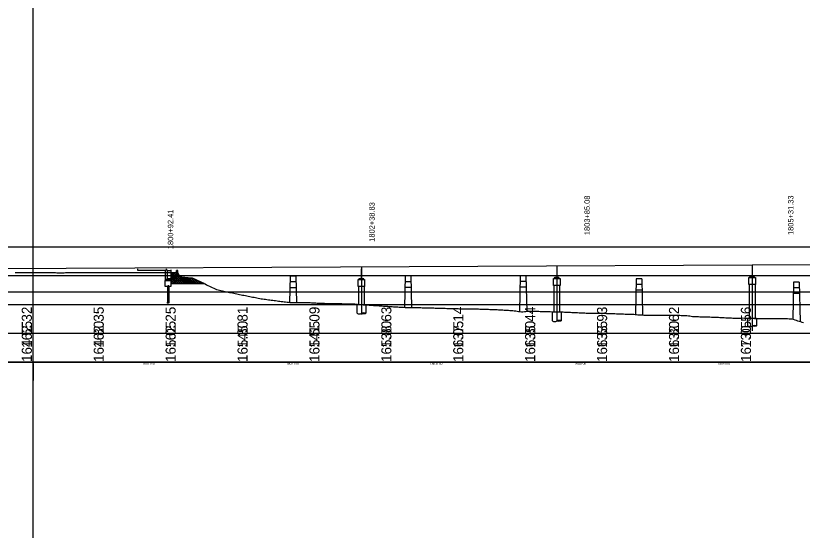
# Model space of a CAD drawing. Extents: x 2126510 to 2136144, y 865066 to 868066.
# Drawn here: x 2128457 to 2129003, y 866497 to 866855 of the extents above; entities that cross this region are included whole.
import ezdxf

# ---------------------------------------------------------------- set-up
doc = ezdxf.new("R2010")
doc.units = 0
for name, color, linetype in [('RD_DTM_BkLn1', 7, 'Continuous'), ('RD_EX_Bldg', 7, 'Continuous'), ('RD_EX_Bridge', 7, 'Continuous'), ('RD_EX_DR_Pipe', 7, 'Continuous'), ('RD_EX_GuardRail', 7, 'Continuous'), ('RD_EX_H2O', 7, 'Continuous'), ('RD_EX_Misc', 7, 'Continuous'), ('RD_EX_Misc_Golf_Fairway', 7, 'Continuous'), ('RD_EX_VEG', 7, 'Continuous'), ('RD_HC_Data', 7, 'Continuous'), ('RD_HC_txCode', 7, 'Continuous')]:
    doc.layers.add(name, color=color, linetype=linetype)

msp = doc.modelspace()

# ---------------------------------------------------------------- linework, layer by layer
at = {"layer": 'RD_DTM_BkLn1'}
for p, q in [((2128541.13, 866678.82), (2128541.13, 866677.82)), ((2128541.13, 866677.82), (2128561.13, 866677.92)), ((2128560.46, 866677.92), (2128560.46, 866670.48)), ((2128561.13, 866678.92), (2128561.13, 866677.92)), ((2128561.79, 866678.19), (2128561.79, 866671.49)), ((2128564.46, 866678.21), (2128564.46, 866670.62)), ((2128564.21, 866671.2), (2128560.71, 866671.2)), ((2128560.71, 866671.2), (2128560.71, 866670.62)), ((2128563.79, 866671.49), (2128561.13, 866671.49)), ((2128561.13, 866671.49), (2128561.13, 866671.2)), ((2128561.13, 866671.2), (2128563.79, 866671.2)), ((2128563.79, 866671.2), (2128563.79, 866671.49)), ((2128564.21, 866670.62), (2128564.21, 866671.2)), ((2128698.63, 866671.87), (2128695.13, 866671.87)), ((2128695.13, 866671.87), (2128695.13, 866671.54)), ((2128695.54, 866671.87), (2128698.21, 866671.87)), ((2128698.63, 866671.54), (2128698.63, 866671.87)), ((2128834.46, 866672.55), (2128830.96, 866672.55)), ((2128830.96, 866672.55), (2128830.96, 866672.22)), ((2128834.04, 866672.84), (2128831.37, 866672.84)), ((2128831.37, 866672.55), (2128834.04, 866672.55)), ((2128834.46, 866672.22), (2128834.46, 866672.55)), ((2128970.3, 866673.23), (2128966.8, 866673.23)), ((2128966.8, 866673.23), (2128966.8, 866672.9)), ((2128967.21, 866673.23), (2128969.88, 866673.23)), ((2128970.3, 866672.9), (2128970.3, 866673.23)), ((2128694.88, 866666.54), (2128694.88, 866654)), ((2128698.88, 866666.54), (2128698.88, 866654)), ((2128830.71, 866667.22), (2128830.71, 866648.91)), ((2128834.71, 866667.22), (2128834.71, 866648.91)), ((2128966.55, 866667.9), (2128966.55, 866644.47)), ((2128970.55, 866667.9), (2128970.55, 866644.47))]:
    msp.add_line(p, q, dxfattribs=at)
for points in [[(2128560.46, 866677.92), (2128561.13, 866677.92)], [(2128693.88, 866647.98), (2128693.88, 866654), (2128699.88, 866654), (2128699.88, 866647.98)], [(2128829.71, 866642.72), (2128829.71, 866648.91), (2128835.71, 866648.91), (2128835.71, 866642.72)], [(2128965.55, 866639.22), (2128965.55, 866644.47), (2128971.55, 866644.47), (2128971.55, 866639.22)]]:
    msp.add_lwpolyline(points, dxfattribs=at)
for points in [[(2128694.63, 866671.54), (2128699.13, 866671.54), (2128699.13, 866666.54), (2128694.63, 866666.54)], [(2128830.46, 866672.22), (2128834.96, 866672.22), (2128834.96, 866667.22), (2128830.46, 866667.22)], [(2128966.3, 866672.9), (2128970.8, 866672.9), (2128970.8, 866667.9), (2128966.3, 866667.9)], [(2128560.46, 866670.62), (2128564.46, 866670.62), (2128564.46, 866666.62), (2128560.46, 866666.62)]]:
    msp.add_lwpolyline(points, close=True, dxfattribs=at)
for centre in [(2128695.38, 866647.98), (2128831.21, 866642.72), (2128967.05, 866639.22)]:
    msp.add_ellipse(centre, major_axis=(-1.5, 0), ratio=0.310397, start_param=0, end_param=3.141593, dxfattribs=at)
for centre in [(2128698.38, 866647.98), (2128834.21, 866642.72), (2128970.05, 866639.22)]:
    msp.add_ellipse(centre, major_axis=(-1.5, 0), ratio=0.310397, dxfattribs=at)
at = {"layer": 'RD_EX_Bldg'}
for p, q in [((2128561.96, 866666.62), (2128561.96, 866655.27)), ((2128562.96, 866666.62), (2128562.96, 866655.27))]:
    msp.add_line(p, q, dxfattribs=at)
msp.add_lwpolyline([(2128563.26, 866655.27), (2128562.71, 866655.27), (2128562.71, 866655.85), (2128562.21, 866654.69), (2128562.21, 866655.27), (2128561.66, 866655.27)], dxfattribs=at)
at = {"layer": 'RD_EX_Bridge'}
for p, q in [((2128695.54, 866672.16), (2128695.54, 866671.87)), ((2128696.54, 866672.16), (2128696.54, 866671.87)), ((2128697.21, 866671.87), (2128697.21, 866672.16)), ((2128698.21, 866671.87), (2128698.21, 866672.16)), ((2128831.37, 866672.84), (2128831.37, 866672.55)), ((2128834.04, 866672.55), (2128834.04, 866672.84)), ((2128967.21, 866673.52), (2128967.21, 866673.23)), ((2128968.21, 866673.52), (2128968.21, 866673.23)), ((2128968.88, 866673.23), (2128968.88, 866673.52)), ((2128969.88, 866673.23), (2128969.88, 866673.52))]:
    msp.add_line(p, q, dxfattribs=at)
at = {"layer": 'RD_EX_DR_Pipe'}
for p, q in [((2128564.46, 866673.36), (2128567.42, 866676.33)), ((2128564.46, 866674.78), (2128565.97, 866676.29)), ((2128564.46, 866676.19), (2128564.54, 866676.28)), ((2128564.46, 866671.95), (2128568.68, 866676.17)), ((2128564.46, 866670.54), (2128569.46, 866675.53)), ((2128564.46, 866675.32), (2128571.15, 866668.62)), ((2128564.46, 866669.12), (2128569.99, 866674.65)), ((2128564.46, 866673.9), (2128569.74, 866668.62)), ((2128564.46, 866672.49), (2128568.32, 866668.62)), ((2128564.46, 866671.07), (2128566.91, 866668.62)), ((2128564.91, 866676.28), (2128572.57, 866668.62)), ((2128565.37, 866668.62), (2128570.58, 866673.83)), ((2128566.3, 866676.3), (2128573.98, 866668.62)), ((2128566.79, 866668.62), (2128571.24, 866673.07)), ((2128567.68, 866676.33), (2128575.39, 866668.62)), ((2128568.2, 866668.62), (2128572.65, 866673.07)), ((2128569.62, 866668.62), (2128574.01, 866673.01)), ((2128571.03, 866668.62), (2128575.29, 866672.88)), ((2128572.36, 866673.07), (2128576.81, 866668.62)), ((2128572.45, 866668.62), (2128576.57, 866672.75)), ((2128573.82, 866673.02), (2128578.22, 866668.62)), ((2128573.86, 866668.62), (2128577.85, 866672.61)), ((2128575.27, 866668.62), (2128579.12, 866672.47)), ((2128575.39, 866672.87), (2128579.64, 866668.62)), ((2128576.69, 866668.62), (2128580.25, 866672.18)), ((2128576.97, 866672.7), (2128581.05, 866668.62)), ((2128578.1, 866668.62), (2128581.2, 866671.72)), ((2128578.55, 866672.53), (2128582.47, 866668.62)), ((2128579.52, 866668.62), (2128582.15, 866671.26)), ((2128580.39, 866672.11), (2128583.88, 866668.62)), ((2128564.46, 866669.66), (2128565.5, 866668.62)), ((2128580.93, 866668.62), (2128583.1, 866670.79)), ((2128582.34, 866668.62), (2128584.05, 866670.33)), ((2128583.15, 866670.77), (2128585.29, 866668.62)), ((2128583.76, 866668.62), (2128585, 866669.86)), ((2128585.17, 866668.62), (2128585.95, 866669.4)), ((2128585.91, 866669.42), (2128586.71, 866668.62)), ((2128586.59, 866668.62), (2128586.9, 866668.94)), ((2128587.54, 866668.62), (2128587.19, 866668.8))]:
    msp.add_line(p, q, dxfattribs=at)
at = {"layer": 'RD_EX_GuardRail'}
for p, q in [((2131097.7, 866693.9), (2126517.45, 866693.9)), ((2128999.96, 866673.9), (2126517.45, 866673.9)), ((2131097.7, 866673.9), (2129000.13, 866673.9)), ((2131097.7, 866653.9), (2126517.45, 866653.9)), ((2131097.7, 866633.9), (2126517.45, 866633.9)), ((2131097.7, 866613.9), (2126517.45, 866613.9))]:
    msp.add_line(p, q, dxfattribs=at)
at = {"layer": 'RD_EX_H2O'}
for points in [[(2128456.19, 866676.22), (2128457.19, 866676.22), (2128458.19, 866676.22), (2128459.19, 866676.22), (2128460.19, 866676.22), (2128461.19, 866676.22), (2128462.19, 866676.22), (2128463.19, 866676.22), (2128464.19, 866676.22), (2128465.19, 866676.22), (2128466.19, 866676.22), (2128467.19, 866676.22), (2128468.19, 866676.22), (2128469.19, 866676.22), (2128470.19, 866676.22), (2128471.19, 866676.22), (2128472.19, 866676.22), (2128473.19, 866676.22), (2128474.19, 866676.22), (2128475.19, 866676.22), (2128476.19, 866676.22), (2128477.19, 866676.22), (2128478.19, 866676.22), (2128479.19, 866676.21), (2128480.19, 866676.21), (2128481.19, 866676.2), (2128482.19, 866676.19), (2128483.19, 866676.19), (2128484.19, 866676.18), (2128485.19, 866676.17), (2128486.19, 866676.17), (2128487.19, 866676.16), (2128488.19, 866676.17), (2128489.19, 866676.17), (2128490.19, 866676.17), (2128491.19, 866676.18), (2128492.19, 866676.18), (2128493.19, 866676.19), (2128494.19, 866676.19), (2128495.19, 866676.19), (2128496.19, 866676.2), (2128497.19, 866676.2), (2128498.19, 866676.2), (2128499.19, 866676.21), (2128500.19, 866676.21), (2128501.19, 866676.21), (2128502.19, 866676.22), (2128503.19, 866676.22), (2128504.19, 866676.22), (2128505.19, 866676.23), (2128506.19, 866676.23), (2128507.19, 866676.23), (2128508.19, 866676.23), (2128509.19, 866676.24), (2128510.19, 866676.24), (2128511.19, 866676.24), (2128512.19, 866676.24), (2128513.19, 866676.24), (2128514.19, 866676.24), (2128515.19, 866676.24), (2128516.19, 866676.24), (2128517.19, 866676.25), (2128518.19, 866676.25), (2128519.19, 866676.25), (2128520.19, 866676.25), (2128521.19, 866676.25), (2128522.19, 866676.25), (2128523.19, 866676.25), (2128524.19, 866676.25), (2128525.19, 866676.25), (2128526.19, 866676.25), (2128527.19, 866676.25), (2128528.19, 866676.25), (2128529.19, 866676.25), (2128530.19, 866676.25), (2128531.19, 866676.26), (2128532.19, 866676.26), (2128533.19, 866676.25), (2128534.19, 866676.25), (2128535.19, 866676.25), (2128536.19, 866676.25), (2128537.19, 866676.25)], [(2128537.19, 866676.25), (2128538.19, 866676.24), (2128539.19, 866676.24), (2128540.19, 866676.24), (2128541.19, 866676.24), (2128542.19, 866676.23), (2128543.19, 866676.23), (2128544.19, 866676.23), (2128545.19, 866676.24), (2128546.19, 866676.24), (2128547.19, 866676.24), (2128548.19, 866676.25), (2128549.19, 866676.25), (2128550.19, 866676.25), (2128551.19, 866676.25), (2128552.19, 866676.26), (2128553.19, 866676.26), (2128554.19, 866676.26), (2128555.19, 866676.26), (2128556.19, 866676.26), (2128557.19, 866676.26), (2128558.19, 866676.27), (2128559.19, 866676.27), (2128560.19, 866676.27), (2128561.19, 866676.27), (2128562.19, 866676.27), (2128563.19, 866676.28), (2128564.19, 866676.28), (2128565.19, 866676.28), (2128566.19, 866676.3), (2128567.19, 866676.32), (2128568.19, 866676.35), (2128569.19, 866675.98), (2128570.19, 866674.31), (2128571.19, 866673.07), (2128572.19, 866673.07), (2128573.19, 866673.06), (2128574.19, 866673), (2128575.19, 866672.89), (2128576.19, 866672.79), (2128577.19, 866672.68), (2128578.19, 866672.57), (2128579.19, 866672.47), (2128580.19, 866672.21), (2128581.19, 866671.73), (2128582.19, 866671.24), (2128583.19, 866670.75), (2128584.19, 866670.26), (2128585.19, 866669.77), (2128586.19, 866669.28), (2128587.19, 866668.8), (2128588.19, 866668.31), (2128589.19, 866667.82), (2128590.19, 866667.33), (2128591.19, 866666.85), (2128592.19, 866666.37), (2128593.19, 866665.9), (2128594.19, 866665.43), (2128595.19, 866664.95), (2128596.19, 866664.48), (2128597.19, 866664.16), (2128598.19, 866663.91), (2128599.19, 866663.69), (2128600.19, 866663.5), (2128601.19, 866663.3), (2128602.19, 866663.11), (2128603.19, 866662.9), (2128604.19, 866662.7), (2128605.19, 866662.49), (2128606.19, 866662.29), (2128607.19, 866662.08), (2128608.19, 866661.87), (2128609.19, 866661.67), (2128610.19, 866661.46), (2128611.19, 866661.26), (2128612.19, 866661.05), (2128613.19, 866660.85), (2128614.19, 866660.64), (2128615.19, 866660.44), (2128616.19, 866660.23), (2128617.19, 866660.03), (2128618.19, 866659.82), (2128619.19, 866659.62), (2128620.19, 866659.43), (2128621.19, 866659.23), (2128622.19, 866659.04), (2128623.19, 866658.85), (2128624.19, 866658.66), (2128625.19, 866658.47), (2128626.19, 866658.28), (2128627.19, 866658.09), (2128628.19, 866657.92), (2128629.19, 866657.78), (2128630.19, 866657.65), (2128631.19, 866657.52), (2128632.19, 866657.38), (2128633.19, 866657.25), (2128634.19, 866657.12), (2128635.19, 866656.98), (2128636.19, 866656.85), (2128637.19, 866656.72)], [(2128637.19, 866656.72), (2128638.19, 866656.58), (2128639.19, 866656.45), (2128640.19, 866656.32), (2128641.19, 866656.18), (2128642.19, 866656.05), (2128643.19, 866655.92), (2128644.19, 866655.78), (2128645.19, 866655.65), (2128646.19, 866655.55), (2128647.19, 866655.47), (2128648.19, 866655.38), (2128649.19, 866655.38), (2128650.19, 866655.38), (2128651.19, 866655.39), (2128652.19, 866655.4), (2128653.19, 866655.4), (2128654.19, 866655.41), (2128655.19, 866655.41), (2128656.19, 866655.42), (2128657.19, 866655.41), (2128658.19, 866655.4), (2128659.19, 866655.39), (2128660.19, 866655.38), (2128661.19, 866655.32), (2128662.19, 866655.25), (2128663.19, 866655.21), (2128664.19, 866655.16), (2128665.19, 866655.12), (2128666.19, 866655.07), (2128667.19, 866655.03), (2128668.19, 866655.01), (2128669.19, 866654.98), (2128670.19, 866654.93), (2128671.19, 866654.87), (2128672.19, 866654.83), (2128673.19, 866654.82), (2128674.19, 866654.8), (2128675.19, 866654.78), (2128676.19, 866654.76), (2128677.19, 866654.74), (2128678.19, 866654.73), (2128679.19, 866654.71), (2128680.19, 866654.69), (2128681.19, 866654.67), (2128682.19, 866654.66), (2128683.19, 866654.64), (2128684.19, 866654.62), (2128685.19, 866654.6), (2128686.19, 866654.59), (2128687.19, 866654.57), (2128688.19, 866654.55), (2128689.19, 866654.53), (2128690.19, 866654.52), (2128691.19, 866654.5), (2128692.19, 866654.42), (2128693.19, 866654.33), (2128694.19, 866654.24), (2128695.19, 866654.15), (2128696.19, 866654.06), (2128697.19, 866653.97), (2128698.19, 866653.9), (2128699.19, 866653.84), (2128700.19, 866653.77), (2128701.19, 866653.7), (2128702.19, 866653.64), (2128703.19, 866653.57), (2128704.19, 866653.5), (2128705.19, 866653.44), (2128706.19, 866653.37), (2128707.19, 866653.31), (2128708.19, 866653.24), (2128709.19, 866653.17), (2128710.19, 866653.11), (2128711.19, 866653.04), (2128712.19, 866652.97), (2128713.19, 866652.91), (2128714.19, 866652.84), (2128715.19, 866652.77), (2128716.19, 866652.71), (2128717.19, 866652.64), (2128718.19, 866652.57), (2128719.19, 866652.51), (2128720.19, 866652.44), (2128721.19, 866652.37), (2128722.19, 866652.31), (2128723.19, 866652.24), (2128724.19, 866652.18), (2128725.19, 866652.13), (2128726.19, 866652.08), (2128727.19, 866652.03), (2128728.19, 866651.98), (2128729.19, 866651.98), (2128730.19, 866651.99), (2128731.19, 866652), (2128732.19, 866652.01), (2128733.19, 866651.98), (2128734.19, 866651.96), (2128735.19, 866651.93), (2128736.19, 866651.9), (2128737.19, 866651.88)], [(2128737.19, 866651.88), (2128738.19, 866651.85), (2128739.19, 866651.82), (2128740.19, 866651.79), (2128741.19, 866651.77), (2128742.19, 866651.74), (2128743.19, 866651.71), (2128744.19, 866651.69), (2128745.19, 866651.66), (2128746.19, 866651.63), (2128747.19, 866651.61), (2128748.19, 866651.58), (2128749.19, 866651.55), (2128750.19, 866651.52), (2128751.19, 866651.5), (2128752.19, 866651.47), (2128753.19, 866651.44), (2128754.19, 866651.42), (2128755.19, 866651.39), (2128756.19, 866651.37), (2128757.19, 866651.34), (2128758.19, 866651.31), (2128759.19, 866651.29), (2128760.19, 866651.26), (2128761.19, 866651.23), (2128762.19, 866651.21), (2128763.19, 866651.18), (2128764.19, 866651.15), (2128765.19, 866651.13), (2128766.19, 866651.1), (2128767.19, 866651.08), (2128768.19, 866651.05), (2128769.19, 866651.03), (2128770.19, 866651), (2128771.19, 866651), (2128772.19, 866650.99), (2128773.19, 866650.98), (2128774.19, 866650.98), (2128775.19, 866650.97), (2128776.19, 866650.96), (2128777.19, 866650.96), (2128778.19, 866650.94), (2128779.19, 866650.91), (2128780.19, 866650.89), (2128781.19, 866650.86), (2128782.19, 866650.83), (2128783.19, 866650.79), (2128784.19, 866650.75), (2128785.19, 866650.71), (2128786.19, 866650.66), (2128787.19, 866650.62), (2128788.19, 866650.58), (2128789.19, 866650.54), (2128790.19, 866650.49), (2128791.19, 866650.45), (2128792.19, 866650.41), (2128793.19, 866650.35), (2128794.19, 866650.29), (2128795.19, 866650.23), (2128796.19, 866650.17), (2128797.19, 866650.11), (2128798.19, 866650.05), (2128799.19, 866649.99), (2128800.19, 866649.93), (2128801.19, 866649.87), (2128802.19, 866649.81), (2128803.19, 866649.7), (2128804.19, 866649.56), (2128805.19, 866649.41), (2128806.19, 866649.26), (2128807.19, 866649.12), (2128808.19, 866648.97), (2128809.19, 866649.01), (2128810.19, 866649.1), (2128811.19, 866649.19), (2128812.19, 866649.29), (2128813.19, 866649.38), (2128814.19, 866649.48), (2128815.19, 866649.45), (2128816.19, 866649.42), (2128817.19, 866649.39), (2128818.19, 866649.36), (2128819.19, 866649.33), (2128820.19, 866649.3), (2128821.19, 866649.28), (2128822.19, 866649.25), (2128823.19, 866649.22), (2128824.19, 866649.19), (2128825.19, 866649.16), (2128826.19, 866649.13), (2128827.19, 866649.11), (2128828.19, 866649.08), (2128829.19, 866649.05), (2128830.19, 866649.02), (2128831.19, 866648.94), (2128832.19, 866648.91), (2128833.19, 866648.91), (2128834.19, 866648.9), (2128835.19, 866648.89), (2128836.19, 866648.87), (2128837.19, 866648.83)], [(2128837.19, 866648.83), (2128838.19, 866648.78), (2128839.19, 866648.74), (2128840.19, 866648.69), (2128841.19, 866648.64), (2128842.19, 866648.6), (2128843.19, 866648.55), (2128844.19, 866648.51), (2128845.19, 866648.46), (2128846.19, 866648.42), (2128847.19, 866648.37), (2128848.19, 866648.32), (2128849.19, 866648.28), (2128850.19, 866648.23), (2128851.19, 866648.19), (2128852.19, 866648.14), (2128853.19, 866648.1), (2128854.19, 866648.05), (2128855.19, 866648.01), (2128856.19, 866648), (2128857.19, 866647.99), (2128858.19, 866647.98), (2128859.19, 866647.97), (2128860.19, 866647.96), (2128861.19, 866647.96), (2128862.19, 866647.95), (2128863.19, 866647.95), (2128864.19, 866647.95), (2128865.19, 866647.95), (2128866.19, 866647.92), (2128867.19, 866647.88), (2128868.19, 866647.85), (2128869.19, 866647.82), (2128870.19, 866647.78), (2128871.19, 866647.75), (2128872.19, 866647.71), (2128873.19, 866647.68), (2128874.19, 866647.64), (2128875.19, 866647.61), (2128876.19, 866647.57), (2128877.19, 866647.54), (2128878.19, 866647.5), (2128879.19, 866647.47), (2128880.19, 866647.43), (2128881.19, 866647.4), (2128882.19, 866647.36), (2128883.19, 866647.33), (2128884.19, 866647.29), (2128885.19, 866647.26), (2128886.19, 866647.23), (2128887.19, 866647.17), (2128888.19, 866647.05), (2128889.19, 866646.94), (2128890.19, 866646.88), (2128891.19, 866646.82), (2128892.19, 866646.77), (2128893.19, 866646.71), (2128894.19, 866646.66), (2128895.19, 866646.63), (2128896.19, 866646.63), (2128897.19, 866646.63), (2128898.19, 866646.63), (2128899.19, 866646.62), (2128900.19, 866646.62), (2128901.19, 866646.62), (2128902.19, 866646.62), (2128903.19, 866646.62), (2128904.19, 866646.62), (2128905.19, 866646.62), (2128906.19, 866646.62), (2128907.19, 866646.62), (2128908.19, 866646.62), (2128909.19, 866646.62), (2128910.19, 866646.62), (2128911.19, 866646.61), (2128912.19, 866646.61), (2128913.19, 866646.61), (2128914.19, 866646.61), (2128915.19, 866646.61), (2128916.19, 866646.61), (2128917.19, 866646.6), (2128918.19, 866646.55), (2128919.19, 866646.5), (2128920.19, 866646.45), (2128921.19, 866646.41), (2128922.19, 866646.36), (2128923.19, 866646.31), (2128924.19, 866646.25), (2128925.19, 866646.1), (2128926.19, 866645.96), (2128927.19, 866645.81), (2128928.19, 866645.66), (2128929.19, 866645.62), (2128930.19, 866645.61), (2128931.19, 866645.59), (2128932.19, 866645.57), (2128933.19, 866645.56), (2128934.19, 866645.54), (2128935.19, 866645.52), (2128936.19, 866645.48), (2128937.19, 866645.44)], [(2128937.19, 866645.44), (2128938.19, 866645.4), (2128939.19, 866645.36), (2128940.19, 866645.32), (2128941.19, 866645.28), (2128942.19, 866645.24), (2128943.19, 866645.2), (2128944.19, 866645.16), (2128945.19, 866645.12), (2128946.19, 866645.07), (2128947.19, 866645.02), (2128948.19, 866644.97), (2128949.19, 866644.93), (2128950.19, 866644.88), (2128951.19, 866644.83), (2128952.19, 866644.78), (2128953.19, 866644.73), (2128954.19, 866644.69), (2128955.19, 866644.64), (2128956.19, 866644.59), (2128957.19, 866644.54), (2128958.19, 866644.49), (2128959.19, 866644.47), (2128960.19, 866644.54), (2128961.19, 866644.6), (2128962.19, 866644.66), (2128963.19, 866644.62), (2128964.19, 866644.59), (2128965.19, 866644.56), (2128966.19, 866644.53), (2128967.19, 866644.51), (2128968.19, 866644.48), (2128969.19, 866644.45), (2128970.19, 866644.42), (2128971.19, 866644.39), (2128972.19, 866644.37), (2128973.19, 866644.34), (2128974.19, 866644.31), (2128975.19, 866644.29), (2128976.19, 866644.28), (2128977.19, 866644.28), (2128978.19, 866644.27), (2128979.19, 866644.27), (2128980.19, 866644.26), (2128981.19, 866644.26), (2128982.19, 866644.25), (2128983.19, 866644.25), (2128984.19, 866644.24), (2128985.19, 866644.24), (2128986.19, 866644.23), (2128987.19, 866644.23), (2128988.19, 866644.22), (2128989.19, 866644.22), (2128990.19, 866644.21), (2128991.19, 866644.21), (2128992.19, 866644.2), (2128993.19, 866644.2), (2128994.19, 866644.19), (2128995.19, 866644.18), (2128996.19, 866644.04), (2128997.19, 866643.73), (2128998.19, 866643.41), (2128999.19, 866643.09), (2129000.19, 866642.76), (2129001.19, 866642.44), (2129002.19, 866642.12), (2129003.19, 866641.8), (2129004.19, 866641.48)]]:
    msp.add_lwpolyline(points, dxfattribs=at)
at = {"layer": 'RD_EX_Misc'}
for p, q in [((2128468.72, 866612.9), (2128468.72, 866698.64)), ((2127961.73, 866676.62), (2129142.37, 866682.52)), ((2127368.72, 866613.9), (2131522.97, 866613.9))]:
    msp.add_line(p, q, dxfattribs=at)
msp.add_lwpolyline([(2127275.85, 866613.9), (2127275.85, 866662.9), (2131989.68, 866662.9)], dxfattribs=at)
at = {"layer": 'RD_EX_Misc_Golf_Fairway'}
for p, q in [((2128468.72, 865065.87), (2128468.72, 867928.23)), ((2128568.28, 866671.01), (2128568.28, 866677.7)), ((2128569.28, 866677.7), (2128568.28, 866677.7)), ((2128569.28, 866673.47), (2128569.28, 866677.7)), ((2128569.28, 866673.47), (2128571.78, 866673.47)), ((2128571.78, 866670.97), (2128571.78, 866673.47)), ((2128647.28, 866673.71), (2128646.9, 866655.49)), ((2128651.28, 866673.71), (2128647.28, 866673.71)), ((2128651.28, 866673.71), (2128651.67, 866655.39)), ((2128727.28, 866673.87), (2128726.83, 866652.05)), ((2128731.28, 866673.87), (2128727.28, 866673.87)), ((2128731.28, 866673.87), (2128731.74, 866652)), ((2128807.28, 866674.03), (2128806.77, 866649.18)), ((2128811.28, 866674.03), (2128807.28, 866674.03)), ((2128811.28, 866674.03), (2128811.8, 866649.25)), ((2128887.91, 866671.95), (2128887.39, 866647.14)), ((2128891.91, 866671.95), (2128887.91, 866671.95)), ((2128891.91, 866671.95), (2128892.43, 866646.76)), ((2128568.28, 866670.97), (2128571.78, 866670.97)), ((2128651.45, 866665.71), (2128647.12, 866665.71)), ((2128651.37, 866669.71), (2128647.21, 866669.71)), ((2128731.45, 866665.87), (2128727.12, 866665.87)), ((2128731.37, 866669.87), (2128727.21, 866669.87)), ((2128811.45, 866666.03), (2128807.12, 866666.03)), ((2128811.37, 866670.03), (2128807.21, 866670.03)), ((2128891.99, 866667.95), (2128887.84, 866667.95)), ((2128997.28, 866669.65), (2128996.75, 866643.87)), ((2129001.37, 866665.65), (2128997.21, 866665.65)), ((2129001.28, 866669.65), (2128997.28, 866669.65)), ((2129001.28, 866669.65), (2129001.85, 866642.23)), ((2128892.07, 866663.95), (2128887.74, 866663.95)), ((2129001.45, 866661.65), (2128997.12, 866661.65)), ((2128468.72, 866612.9), (2128468.72, 866601.12))]:
    msp.add_line(p, q, dxfattribs=at)
at = {"layer": 'RD_EX_VEG'}
msp.add_line((2128564.46, 866668.62), (2128587.64, 866668.62), dxfattribs=at)
at = {"layer": 'RD_HC_Data'}
for p, q in [((2128696.88, 866680.29), (2128696.88, 866647.1)), ((2128832.71, 866680.97), (2128832.71, 866642.13)), ((2128968.55, 866681.65), (2128968.55, 866635.79)), ((2128562.46, 866667.55), (2128562.46, 866655.27))]:
    msp.add_line(p, q, dxfattribs=at)
at = {"layer": 'RD_HC_txCode'}
for p, q in [((2128561.79, 866677.7), (2128564.46, 866677.71)), ((2128696.79, 866678.87), (2128696.79, 866672.16)), ((2128696.96, 866678.87), (2128696.96, 866672.16)), ((2128968.46, 866680.23), (2128968.46, 866673.52)), ((2128968.63, 866680.23), (2128968.63, 866673.52)), ((2128561.79, 866672.07), (2128564.46, 866672.08)), ((2128561.79, 866671.49), (2128564.46, 866671.5))]:
    msp.add_line(p, q, dxfattribs=at)

# ---------------------------------------------------------------- texts
at = {"layer": 'RD_EX_Misc'}
for s, height, p in [('1803+85.08', 3.75, (2128855.67, 866702.29)), ('1805+31.33', 3.75, (2128997.28, 866702.35)), ('1802+38.83', 3.75, (2128706.07, 866697.67)), ('1800+92.41', 3.75, (2128566.01, 866692.53)), ('162.32', 7, (2128467.72, 866623.9)), ('162.35', 7, (2128517.72, 866623.9)), ('162.25', 7, (2128567.72, 866623.9)), ('145.81', 7, (2128617.72, 866623.9)), ('141.09', 7, (2128667.72, 866623.9)), ('138.63', 7, (2128717.72, 866623.9)), ('137.14', 7, (2128767.72, 866623.9)), ('135.44', 7, (2128817.72, 866623.9)), ('133.93', 7, (2128867.72, 866623.9)), ('132.62', 7, (2128917.72, 866623.9)), ('130.56', 7, (2128967.72, 866623.9)), ('164.55', 7, (2128467.72, 866614.05)), ('164.80', 7, (2128517.72, 866614.05)), ('165.05', 7, (2128567.72, 866614.05)), ('165.30', 7, (2128617.72, 866614.05)), ('165.55', 7, (2128667.72, 866614.05)), ('165.80', 7, (2128717.72, 866614.05)), ('166.05', 7, (2128767.72, 866614.05)), ('166.30', 7, (2128817.72, 866614.05)), ('166.55', 7, (2128867.72, 866614.05)), ('166.80', 7, (2128917.72, 866614.05)), ('167.05', 7, (2128967.72, 866614.05))]:
    msp.add_text(s, height=height, rotation=90, dxfattribs=at).set_placement(p)
for s, p in [('1801+00', (2128544.51, 866612.1)), ('1802+00', (2128644.51, 866612.1)), ('1803+00', (2128744.51, 866612.1)), ('1804+00', (2128844.51, 866612.1)), ('1805+00', (2128944.51, 866612.1))]:
    msp.add_text(s, height=1.6, dxfattribs=at).set_placement(p)

doc.saveas('drawing.dxf')
